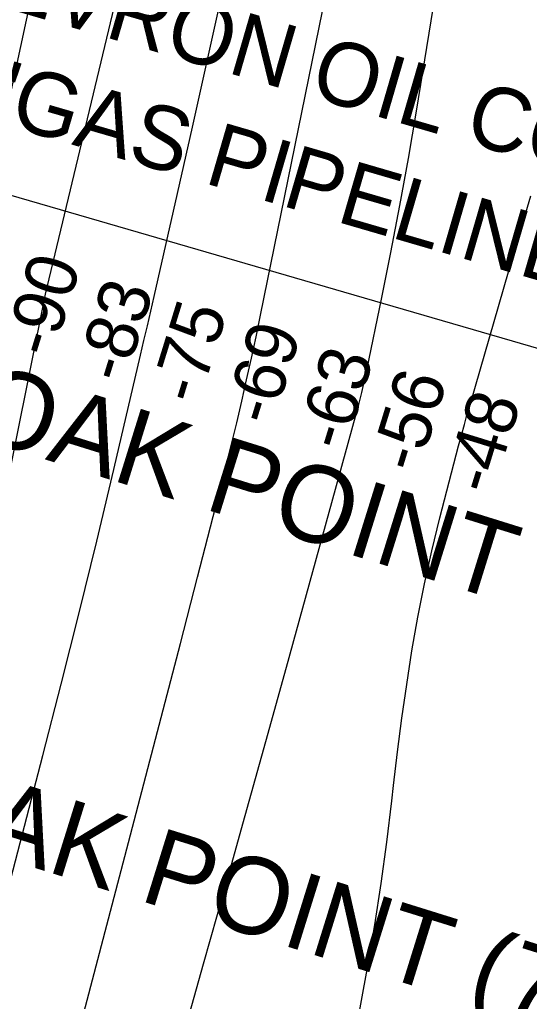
# Model space of a CAD drawing. Extents: x 3683613 to 3738215, y 469626 to 495384.
# Drawn here: x 3702169 to 3702833, y 477641 to 478919 of the extents above; entities that cross this region are included whole.
import ezdxf

# ---------------------------------------------------------------- set-up
doc = ezdxf.new("R2010")
doc.units = 0
for name, color, linetype in [('V-CHAN-NAID', 7, 'Continuous'), ('V-RIVR-RANG', 7, 'Continuous'), ('V-TOPO-MAJR', 7, 'Continuous'), ('V-TOPO-MINR', 7, 'Continuous'), ('V-UTIL-IDEN', 7, 'Continuous'), ('V-UTIL-LINE', 7, 'Continuous')]:
    doc.layers.add(name, color=color, linetype=linetype)

msp = doc.modelspace()

# ---------------------------------------------------------------- linework, layer by layer
at = {"layer": 'V-TOPO-MAJR'}
for points in [[(3702107.13, 478591.57), (3702280.33, 479395.29000000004), (3702374.945637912, 479950.26529274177), (3702386.8374688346, 480019.90847855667), (3702398.753431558, 480089.5475287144), (3702410.7055919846, 480159.1803753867), (3702422.6818842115, 480228.8090864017), (3702439.941008, 480328.9956652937), (3702443.3244742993, 480348.52471340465), (3702446.732789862, 480368.0493992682), (3702450.1783793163, 480387.5675417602), (3702453.6488180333, 480407.0813220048), (3702474.9748315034, 480526.3339233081), (3702489.286492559, 480605.44108535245), (3702503.810916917, 480684.50871937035), (3702518.65448623, 480763.51706134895), (3702533.710818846, 480842.48587530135)], [(3702584.156880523, 477477.73449058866), (3702622.4421212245, 477686.70603353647), (3702631.657207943, 477740.2504384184), (3702640.100931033, 477793.9077332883), (3702647.3876086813, 477847.73436314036), (3702653.902922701, 477901.67388298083), (3702656.096143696, 477921.63408864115), (3702661.2766672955, 477965.6318409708), (3702666.911555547, 478009.5677304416), (3702673.2279907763, 478053.41082562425), (3702679.998790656, 478097.1920579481), (3702687.715053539, 478140.7995182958), (3702696.235868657, 478184.2374848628), (3702705.9635121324, 478227.42121075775), (3702716.495707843, 478270.4354428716), (3702740.8038969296, 478364.0451240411), (3702744.4705599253, 478377.9235907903), (3702748.21531416, 478391.7805989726), (3702752.077205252, 478405.6054193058), (3702756.0171875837, 478419.4087810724), (3702805.650925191, 478590.54874679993), (3702834.5974341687, 478689.8673527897)]]:
    msp.add_lwpolyline(points, dxfattribs=at)
at = {"layer": 'V-TOPO-MINR'}
for points in [[(3702143.801942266, 478267.75803847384), (3702202.6, 478561.82), (3702389.7979485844, 479343.04868594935), (3702391.9445533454, 479352.2018513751), (3702394.032088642, 479361.36816962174), (3702396.031019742, 479370.55421709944), (3702397.970881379, 479379.7534173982), (3702411.711437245, 479446.50855534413), (3702420.3788306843, 479489.11466458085), (3702428.9149846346, 479531.7467368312), (3702437.254279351, 479574.417753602), (3702445.4623345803, 479617.11473338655), (3702580.39, 480327.83), (3702617.7961604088, 480575.338029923), (3702633.707713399, 480682.4676531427), (3702649.2550440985, 480789.64916191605), (3702664.25604136, 480896.90849901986)], [(3702369.0399460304, 477548.4254799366), (3702408.686128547, 477689.36490221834), (3702435.784719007, 477785.95340050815), (3702462.79466109, 477882.56661628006), (3702489.671630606, 477979.2169082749), (3702516.459951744, 478075.89191775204), (3702606.6400777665, 478402.2106925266), (3702610.772244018, 478417.75575949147), (3702614.6998477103, 478433.3502175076), (3702618.320607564, 478449.0187621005), (3702621.7368048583, 478464.73669774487), (3702640.4497201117, 478555.0998209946), (3702652.677370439, 478616.1087911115), (3702664.383290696, 478677.21425335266), (3702675.306615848, 478738.4644537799), (3702685.708210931, 478799.8111463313), (3702759.47, 479252.39), (3703008.3251678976, 480130.647789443), (3703017.225575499, 480162.18693738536), (3703026.081210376, 480193.73860035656), (3703034.869686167, 480225.3090358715), (3703043.6133892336, 480256.8919864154), (3703179.280690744, 480748.9685062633), (3703193.374171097, 480799.74478107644)], [(3702250.1255523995, 477615.68458748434), (3702257.0527282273, 477642.16129392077), (3702263.989483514, 477668.6354922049), (3702270.932625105, 477695.1080183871), (3702310.967353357, 477847.63833801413), (3702333.5765576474, 477934.00427220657), (3702356.1117294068, 478020.3894683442), (3702378.535852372, 478106.8035573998), (3702400.885942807, 478193.2369084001), (3702431.1299253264, 478310.5087896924), (3702438.1945407, 478338.3470087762), (3702445.115230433, 478366.2203726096), (3702451.8200317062, 478394.14645356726), (3702458.380907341, 478422.10767927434), (3702464.725824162, 478450.11871345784), (3702470.9267612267, 478478.1610050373), (3702476.9117286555, 478506.25018271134), (3702482.752716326, 478534.3706177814), (3702572.5575399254, 478975.23256899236)], [(3702116.0108747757, 477641.4156975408), (3702199.384062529, 477960.58453335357), (3702223.29743342, 478053.5825433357), (3702246.7355612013, 478146.6982459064), (3702269.460824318, 478239.9904873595), (3702291.7108443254, 478333.40042140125), (3702326.559909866, 478482.2263091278), (3702331.0084877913, 478501.31628752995), (3702335.4298277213, 478520.41254163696), (3702339.8103106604, 478539.518209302), (3702344.163555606, 478558.63015267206), (3702374.572498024, 478692.7962663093), (3702394.0140092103, 478779.0173088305), (3702413.3278201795, 478865.26679836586), (3702432.4500808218, 478951.5589584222)]]:
    msp.add_lwpolyline(points, dxfattribs=at)
at = {"layer": 'V-UTIL-LINE'}
msp.add_lwpolyline([(3703988.1410000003, 478158.438), (3701413.6890000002, 478906.251)], dxfattribs=at)

# ---------------------------------------------------------------- texts
at = {"layer": 'V-CHAN-NAID'}
for p in [(3701428.375099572, 478587.56215666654), (3701343.8460111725, 478077.73174420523)]:
    msp.add_text('CHEVRON OAK POINT (72.3) (2)', height=100.00000200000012, rotation=342.68835389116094, dxfattribs=at).set_placement(p)
at = {"layer": 'V-RIVR-RANG'}
for s, p in [('-90', (3702211.2500162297, 478476.31973082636)), ('-83', (3702305.7088218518, 478443.2893881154)), ('-75', (3702401.8027106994, 478415.55259901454)), ('-69', (3702497.9744606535, 478388.0668362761)), ('-63', (3702592.433266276, 478355.0364935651)), ('-56', (3702688.215710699, 478326.29159901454)), ('-48', (3702784.1548773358, 478298.0497571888))]:
    msp.add_text(s, height=66.99999999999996, rotation=72.8319722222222, dxfattribs=at).set_placement(p)
at = {"layer": 'V-UTIL-IDEN'}
for s, p in [('CHEVRON OIL CO.', (3701981.6916347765, 478983.4343689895)), ('3"GAS PIPELINE', (3702055.848661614, 478809.26989793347))]:
    msp.add_text(s, height=82.99983200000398, rotation=343.7531026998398, dxfattribs=at).set_placement(p)

doc.saveas('drawing.dxf')
